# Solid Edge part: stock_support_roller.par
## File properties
Title: Solid Edge 20
Author: vicky raina
Template: Normal.par
Last saved by: Robert a Rhodes jr
Revision: 9
Application: Solid Edge
Material: aluminum
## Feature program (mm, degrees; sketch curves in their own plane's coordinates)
sketch for "unnamed RevolvedProtrusion 1" plane through (0, 0, 0) normal (0, -1, 0) x-axis (1, 0, 0)
  line (60, 0) -> (60, 18.669)
  line (60, 18.669) -> (15.55, 18.669)
  line (15.55, 18.669) -> (15.55, 92.075)
  line (15.55, 92.075) -> (-2.2388, 92.075)
  line (-2.2388, 92.075) -> (-111.45, 29.0219)
  line (-220.6612, 92.075) -> (-111.45, 29.0219)
  line (-238.45, 92.075) -> (-220.6612, 92.075)
  line (-238.45, 18.669) -> (-238.45, 92.075)
  line (-282.9, 18.669) -> (-238.45, 18.669)
  line (-282.9, 0) -> (-282.9, 18.669)
revolve "unnamed RevolvedProtrusion 1" add full turn 360 deg about sketch line (-282.9, 0) -> (60, 0)
chamfer "unnamed Chamfer 1"
fillet "unnamed Round 1"
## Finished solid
Body 1: solid body, 14 faces, 13 edges, 0 vertices.
  Faces by surface: cone 4, cylinder 4, plane 4, torus 2
  Edges by curve: circle 13
Bounding box of the edges (mm; curved faces can reach further): 342.900 x 184.150 x 184.150, from (-282.9, -92.075, -92.075) to (60, 92.075, 92.075).
Cylindrical faces by radius (mm): R18.669 x2, R92.075 x2
Conical faces (half-angle, radius in mm at the cone's reference point): 30 deg R29.0219 x1, 30 deg R92.075 x1, 45 deg R17.0942 x1, 45 deg R18.669 x1
Toroidal faces (ring radius, tube radius in mm): R20.2438 r1.5748 x2
Planar faces by outward normal: +x 2, -x 2
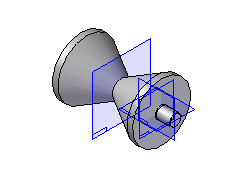
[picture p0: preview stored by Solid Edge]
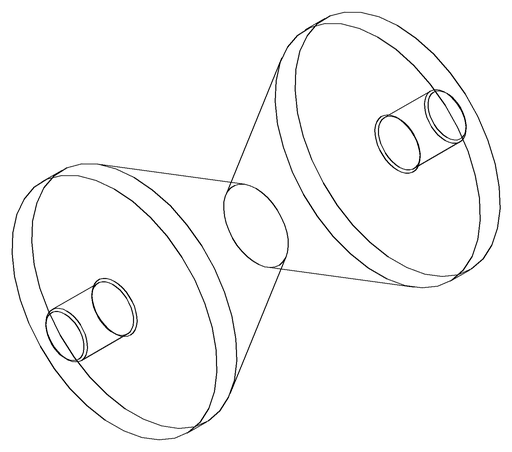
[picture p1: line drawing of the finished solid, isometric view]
